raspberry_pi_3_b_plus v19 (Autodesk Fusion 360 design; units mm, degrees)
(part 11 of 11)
sketch "Sketch3" plane through (0, 0, -5) normal (0, 0, -1) x axis (1, 0, 0)
  line L1 (-45.553, 29.75) -> (-52.5, 29.75)
  line L2 (-45.553, -29.75) -> (-45.553, 29.75)
  line L3 (-52.5, -29.75) -> (-45.553, -29.75)
  line L4 (-52.5, 29.75) -> (-52.5, -29.75)
  line L5 (44.5, 29.75) -> (-52.5, 29.75)
  line L6 (-52.5, 29.75) -> (-52.5, 24)
  line L7 (-42.0889, 24) -> (-43.8209, 21)
  line L8 (-43.8209, 27) -> (-42.0889, 24)
  line L9 (-47.2851, 27) -> (-43.8209, 27)
  line L10 (-49.0171, 24) -> (-47.2851, 27)
  line L11 (-47.2851, 21) -> (-49.0171, 24)
  line L12 (-43.8209, 21) -> (-47.2851, 21)
  line L13 (-43.8209, 19) -> (-42.0889, 16)
  line L14 (-49.0171, 16) -> (-47.2851, 19)
  line L15 (-47.2851, 19) -> (-43.8209, 19)
  line L16 (-47.2851, 13) -> (-49.0171, 16)
  line L17 (-43.8209, 13) -> (-47.2851, 13)
  line L18 (-42.0889, 16) -> (-43.8209, 13)
  line L19 (-43.8209, 11) -> (-42.0889, 8)
  line L20 (-49.0171, 8) -> (-47.2851, 11)
  line L21 (-47.2851, 11) -> (-43.8209, 11)
  line L22 (-47.2851, 5) -> (-49.0171, 8)
  line L23 (-43.8209, 5) -> (-47.2851, 5)
  line L24 (-42.0889, 8) -> (-43.8209, 5)
  line L25 (-43.8209, 3) -> (-42.0889, 0)
  line L26 (-49.0171, 0) -> (-47.2851, 3)
  line L27 (-47.2851, 3) -> (-43.8209, 3)
  line L28 (-47.2851, -3) -> (-49.0171, 0)
  line L29 (-43.8209, -3) -> (-47.2851, -3)
  line L30 (-42.0889, 0) -> (-43.8209, -3)
  line L31 (-43.8209, -5) -> (-42.0889, -8)
  line L32 (-49.0171, -8) -> (-47.2851, -5)
  line L33 (-47.2851, -5) -> (-43.8209, -5)
  line L34 (-47.2851, -11) -> (-49.0171, -8)
  line L35 (-43.8209, -11) -> (-47.2851, -11)
  line L36 (-42.0889, -8) -> (-43.8209, -11)
  line L37 (-43.8209, -13) -> (-42.0889, -16)
  line L38 (-49.0171, -16) -> (-47.2851, -13)
  line L39 (-47.2851, -13) -> (-43.8209, -13)
  line L40 (-47.2851, -19) -> (-49.0171, -16)
  line L41 (-43.8209, -19) -> (-47.2851, -19)
  line L42 (-42.0889, -16) -> (-43.8209, -19)
  line L43 (-43.8209, -21) -> (-42.0889, -24)
  line L44 (-49.0171, -24) -> (-47.2851, -21)
  line L45 (-47.2851, -21) -> (-43.8209, -21)
  line L46 (-47.2851, -27) -> (-49.0171, -24)
  line L47 (-43.8209, -27) -> (-47.2851, -27)
  line L48 (-42.0889, -24) -> (-43.8209, -27)
  line L49 (-41.2229, 21.5) -> (-42.9549, 22.5)
  line L50 (-41.2229, 18.5) -> (-42.9549, 17.5)
  line L51 (-38.6248, 20) -> (-41.2229, 18.5)
  line L52 (-38.6248, 20) -> (-41.2229, 21.5)
  line L53 (-40.3568, 17) -> (-42.0889, 20)
  line L54 (-36.8927, 17) -> (-40.3568, 17)
  line L55 (-35.1607, 20) -> (-36.8927, 17)
  line L56 (-36.8927, 23) -> (-35.1607, 20)
  line L57 (-40.3568, 23) -> (-36.8927, 23)
  line L58 (-42.0889, 20) -> (-40.3568, 23)
  line L59 (-40.3568, 15) -> (-36.8927, 15)
  line L60 (-36.8927, 15) -> (-35.1607, 12)
  line L61 (-35.1607, 12) -> (-36.8927, 9)
  line L62 (-36.8927, 9) -> (-40.3568, 9)
  line L63 (-40.3568, 9) -> (-42.0889, 12)
  line L64 (-42.0889, 12) -> (-40.3568, 15)
  line L65 (-40.3568, 7) -> (-36.8927, 7)
  line L66 (-36.8927, 7) -> (-35.1607, 4)
  line L67 (-35.1607, 4) -> (-36.8927, 1)
  line L68 (-36.8927, 1) -> (-40.3568, 1)
  line L69 (-40.3568, 1) -> (-42.0889, 4)
  line L70 (-42.0889, 4) -> (-40.3568, 7)
  line L71 (-40.3568, -1) -> (-36.8927, -1)
  line L72 (-36.8927, -1) -> (-35.1607, -4)
  line L73 (-35.1607, -4) -> (-36.8927, -7)
  line L74 (-36.8927, -7) -> (-40.3568, -7)
  line L75 (-40.3568, -7) -> (-42.0889, -4)
  line L76 (-42.0889, -4) -> (-40.3568, -1)
  line L77 (-40.3568, -9) -> (-36.8927, -9)
  line L78 (-36.8927, -9) -> (-35.1607, -12)
  line L79 (-35.1607, -12) -> (-36.8927, -15)
  line L80 (-36.8927, -15) -> (-40.3568, -15)
  line L81 (-40.3568, -15) -> (-42.0889, -12)
  line L82 (-42.0889, -12) -> (-40.3568, -9)
  line L83 (-40.3568, -17) -> (-36.8927, -17)
  line L84 (-36.8927, -17) -> (-35.1607, -20)
  line L85 (-35.1607, -20) -> (-36.8927, -23)
  line L86 (-36.8927, -23) -> (-40.3568, -23)
  line L87 (-40.3568, -23) -> (-42.0889, -20)
  line L88 (-42.0889, -20) -> (-40.3568, -17)
  line L89 (-23.0367, 9) -> (-26.5008, 9)
  line L90 (-29.9649, 11) -> (-28.2329, 8)
  line L91 (-28.2329, -16) -> (-29.9649, -19)
  line L92 (-35.1611, 8) -> (-33.4291, 11)
  line L93 (-29.9649, 13) -> (-33.4291, 13)
  line L94 (-35.1611, -16) -> (-33.4291, -13)
  line L95 (-29.9649, 21) -> (-33.4291, 21)
  line L96 (-26.5008, 23) -> (-23.0367, 23)
  line L97 (-23.0367, 17) -> (-26.5008, 17)
  line L98 (-26.5008, 17) -> (-28.2329, 20)
  line L99 (-29.9649, 19) -> (-28.2329, 16)
  line L100 (-26.5008, 15) -> (-23.0367, 15)
  line L101 (-26.5008, 7) -> (-23.0367, 7)
  line L102 (-23.0367, -7) -> (-26.5008, -7)
  line L103 (-28.2329, -12) -> (-26.5008, -9)
  line L104 (-33.4291, 21) -> (-35.1611, 24)
  line L105 (-21.3047, -20) -> (-23.0367, -23)
  line L106 (-21.3047, 4) -> (-23.0367, 1)
  line L107 (-21.3047, 12) -> (-23.0367, 9)
  line L108 (-33.4291, -5) -> (-29.9649, -5)
  line L109 (-33.4291, -3) -> (-35.1611, 0)
  line L110 (-29.9649, -11) -> (-33.4291, -11)
  line L111 (-21.3047, -12) -> (-23.0367, -15)
  line L112 (-26.5008, -7) -> (-28.2329, -4)
  line L113 (-28.2329, -20) -> (-26.5008, -17)
  line L114 (-33.4291, 19) -> (-29.9649, 19)
  line L115 (-23.0367, -17) -> (-21.3047, -20)
  line L116 (-29.9649, -13) -> (-28.2329, -16)
  line L117 (-33.4291, 27) -> (-29.9649, 27)
  line L118 (-21.3047, -4) -> (-23.0367, -7)
  line L119 (-26.5008, 1) -> (-28.2329, 4)
  line L120 (-28.2329, -8) -> (-29.9649, -11)
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  point P14 (-45.553, 24)
  point P63 (-42.9549, 22.5)
  point P65 (-42.9549, 17.5)
  point P67 (-38.6248, 20)
  point P74 (-38.6248, 20)
  point P395 (-34.5, -1.25)
  point P642 (-34.5, -1.25)
  point P64 (-41.2229, 21.5)
  point P66 (-41.2229, 18.5)
  point P643 (-34.5, 4.75)
  point P644 (-59.5, 4.75)
  point P645 (50.5, 4.75)
  point P647 (-59.5, -7.25)
  horizontal L1
  vertical L2
  horizontal L3
  vertical L4
  horizontal L5
  vertical L6
  coincident L2 P14
  midpoint L7 P63
  perpendicular L7 L49
  midpoint L13 P65
  perpendicular L13 L50
  parallel L50 L51
  perpendicular L7 L52
  coincident P67 P74
  coincident P395 P642
  dimension "d18" = 14.25
  dimension "d18" = 14.25
  dimension "d720" distance P14 L12 = 3
  dimension "d725" distance P63 P64 = 2
  dimension "d726" distance P65 P66 = 2
  dimension "d727" distance P74 L58 = 3
  dimension "d756" distance P642 P643 = 6
  dimension "d757" distance P643 P644 = 25
  dimension "d758" distance P644 P645 = 110
  dimension "d759" distance P644 P647 = 12
  dimension "d718" distance = 6.947
  dimension "d719" distance = 5.75
  dimension "d723" R-Pattern1-uDistance = 0
  dimension "d724" R-Pattern1-vDistance = -8
  dimension "d730" R-Pattern2-uDistance = 0
  dimension "d731" R-Pattern2-vDistance = -8
sketch "Sketch4" plane through (0, 0, 20) normal (0, 0, 1) x axis (-1, 0, 0)
  line L1 (-14.5, 1.25) -> (-30.5, 1.25)
  line L2 (-14.5, -3.75) -> (-14.5, 1.25)
  line L3 (-30.5, -3.75) -> (-14.5, -3.75)
  line L4 (-30.5, 1.25) -> (-30.5, -3.75)
  line L5 (-44.5, -26.75) -> (-44.5, 26.75)
  line L6 (42.5, 1.25) -> (26.5, 1.25)
  line L7 (42.5, -3.75) -> (42.5, 1.25)
  line L8 (26.5, -3.75) -> (42.5, -3.75)
  line L9 (26.5, 1.25) -> (26.5, -3.75)
  line L10 (-0.7829, 5.1511) -> (-0.7829, 28.1511)
  line L11 (-4.7829, 5.1511) -> (-0.7829, 5.1511)
  line L12 (-4.7829, 28.1511) -> (-4.7829, 5.1511)
  line L13 (-0.7829, 28.1511) -> (-4.7829, 28.1511)
  line L14 (2.3829, -5) -> (5.8471, -5)
  line L15 (-32.2568, -17) -> (-28.7927, -17)
  line L16 (-20.1329, 8) -> (-21.8649, 5)
  line L17 (-32.2568, -15) -> (-33.9889, -12)
  line L18 (28.3629, 0) -> (30.0949, 3)
  line L19 (-14.9367, 7) -> (-13.2047, 4)
  line L20 (-21.8649, -19) -> (-25.3291, -19)
  line L21 (-25.3291, -13) -> (-21.8649, -13)
  line L22 (-33.9889, -20) -> (-32.2568, -17)
  line L23 (-6.2769, 4) -> (-4.5448, 7)
  line L24 (-33.9889, 8) -> (-35.7209, 5)
  line L25 (2.3829, -13) -> (5.8471, -13)
  line L26 (33.5591, 3) -> (35.2911, 0)
  line L27 (19.7031, 3) -> (21.4351, 0)
  line L28 (2.3829, 5) -> (0.6509, 8)
  line L29 (-11.4731, 5) -> (-13.2051, 8)
  line L30 (-1.0807, 7) -> (0.6513, 4)
  line L31 (-40.9171, -16) -> (-39.1851, -13)
  line L32 (-28.7927, -15) -> (-32.2568, -15)
  line L33 (-27.0611, -24) -> (-25.3291, -21)
  line L34 (-28.7927, 7) -> (-27.0607, 4)
  line L35 (47.4151, 3) -> (49.1471, 0)
  line L36 (37.0232, 1) -> (35.2911, 4)
  line L37 (-27.0607, -20) -> (-28.7927, -23)
  line L38 (-25.3291, 5) -> (-27.0611, 8)
  line L39 (-33.9889, 4) -> (-32.2568, 7)
  line L40 (-28.7927, -17) -> (-27.0607, -20)
  line L41 (-1.0807, -9) -> (0.6513, -12)
  line L42 (14.5073, 4) -> (12.7753, 1)
  line L43 (-40.9171, -24) -> (-39.1851, -21)
  line L44 (-20.1329, 4) -> (-18.4008, 7)
  line L45 (-21.8649, 21) -> (-25.3291, 21)
  line L46 (-33.9889, -12) -> (-32.2568, -9)
  line L47 (-20.1329, -12) -> (-18.4008, -9)
  line L48 (14.5069, -16) -> (16.2389, -13)
  line L49 (16.2389, -21) -> (19.7031, -21)
  line L50 (9.3112, 1) -> (7.5791, 4)
  line L51 (-39.1851, -19) -> (-40.9171, -16)
  line L52 (14.5069, 0) -> (16.2389, 3)
  line L53 (-21.8649, 13) -> (-25.3291, 13)
  line L54 (-18.4008, -7) -> (-20.1329, -4)
  line L55 (-14.9367, -9) -> (-13.2047, -12)
  line L56 (-39.1851, 5) -> (-40.9171, 8)
  line L57 (28.3633, 4) -> (26.6313, 1)
  line L58 (-18.4008, -23) -> (-20.1329, -20)
  line L59 (43.9509, -13) -> (47.4151, -13)
  line L60 (-6.2769, -12) -> (-4.5448, -9)
  line L61 (-25.3291, 11) -> (-21.8649, 11)
  line L62 (42.2189, 0) -> (43.9509, 3)
  line L63 (-28.7927, -23) -> (-32.2568, -23)
  line L64 (-25.3291, 19) -> (-21.8649, 19)
  line L65 (-25.3291, 27) -> (-21.8649, 27)
  line L66 (5.8471, -13) -> (7.5791, -16)
  line L67 (42.2193, 4) -> (40.4873, 1)
  line L68 (-6.2769, 8) -> (-8.0089, 5)
  line L69 (-28.7927, -9) -> (-27.0607, -12)
  line L70 (23.1672, 1) -> (21.4351, 4)
  line L71 (-18.4008, 1) -> (-20.1329, 4)
  line L72 (5.8471, 3) -> (7.5791, 0)
  line L73 (-25.3291, -21) -> (-21.8649, -21)
  line L74 (-35.7209, -21) -> (-33.9889, -24)
  line L75 (28.3629, 16) -> (30.0949, 19)
  line L76 (-21.8649, -13) -> (-20.1329, -16)
  line L77 (28.3629, 8) -> (30.0949, 11)
  line L78 (16.2389, 27) -> (19.7031, 27)
  line L79 (47.4151, -19) -> (43.9509, -19)
  line L80 (-4.5448, 23) -> (-1.0807, 23)
  line L81 (-20.1329, -4) -> (-18.4008, -1)
  line L82 (-39.1851, -21) -> (-35.7209, -21)
  line L83 (47.4151, -3) -> (43.9509, -3)
  line L84 (9.3112, -17) -> (12.7753, -17)
  line L85 (30.0949, 5) -> (28.3629, 8)
  line L86 (-1.0807, 17) -> (-4.5448, 17)
  line L87 (-33.9889, 16) -> (-35.7209, 13)
  line L88 (-21.8649, -27) -> (-25.3291, -27)
  line L89 (-14.9367, -7) -> (-18.4008, -7)
  line L90 (43.9509, -5) -> (47.4151, -5)
  line L91 (30.0949, 21) -> (28.3629, 24)
  line L92 (-18.4008, -15) -> (-20.1329, -12)
  line L93 (-18.4008, -1) -> (-14.9367, -1)
  line L94 (14.5073, -12) -> (12.7753, -15)
  line L95 (-11.4731, 19) -> (-8.0089, 19)
  line L96 (-25.3291, -19) -> (-27.0611, -16)
  line L97 (9.3112, -23) -> (7.5791, -20)
  line L98 (-39.1851, 13) -> (-40.9171, 16)
  line L99 (-8.0089, 27) -> (-6.2769, 24)
  line L100 (-39.1851, -27) -> (-40.9171, -24)
  line L101 (30.0949, 13) -> (28.3629, 16)
  line L102 (-35.7209, 11) -> (-33.9889, 8)
  line L103 (-6.2769, 0) -> (-8.0089, -3)
  line L104 (19.7031, 5) -> (16.2389, 5)
  line L105 (-35.7209, 19) -> (-33.9889, 16)
  line L106 (-32.2568, 15) -> (-28.7927, 15)
  line L107 (28.3629, 24) -> (30.0949, 27)
  line L108 (21.4351, -16) -> (19.7031, -19)
  line L109 (-35.7209, -19) -> (-39.1851, -19)
  line L110 (35.2911, 16) -> (33.5591, 13)
  line L111 (-20.1329, -16) -> (-21.8649, -19)
  line L112 (12.7753, -23) -> (9.3112, -23)
  line L113 (-8.0089, 11) -> (-6.2769, 8)
  line L114 (0.6513, 4) -> (-1.0807, 1)
  line L115 (-25.3291, 13) -> (-27.0611, 16)
  line L116 (-20.1329, -20) -> (-18.4008, -17)
  line L117 (19.7031, -19) -> (16.2389, -19)
  line L118 (-32.2568, -23) -> (-33.9889, -20)
  line L119 (-11.4731, 27) -> (-8.0089, 27)
  line L120 (-33.9889, -24) -> (-35.7209, -27)
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  point P147 (-34.8549, 17.5)
  point P23 (-30.5248, 20)
  point P24 (-30.5248, 20)
  point P10 (42.5, -3.75)
  point P633 (42.5, -3.75)
  point P8 (26.5, 1.25)
  point P634 (26.5, 1.25)
  point P136 (-34.8549, 22.5)
  point P137 (-33.1229, 21.5)
  point P149 (-33.1229, 18.5)
  point P635 (34.5, -1.25)
  point P636 (34.5, -7.25)
  point P637 (59, -7.25)
  point P638 (-51, -7.25)
  point P640 (59, 4.75)
  midpoint P147 L105
  coincident P23 P24
  coincident P10 P633
  coincident P8 P634
  dimension "d748" distance = 3
  dimension "d749" distance P136 P137 = 2
  dimension "d750" distance P147 P149 = 2
  dimension "d751" distance = 3
  dimension "d762" distance P635 P636 = 6
  dimension "d763" distance P637 P638 = 110
  dimension "d764" distance P637 P640 = 12
  dimension "d742" R-Pattern1-uDistance = 0
  dimension "d743" R-Pattern1-vDistance = -8
extrude "Extrude31" cut sketch "Sketch3" against normal blind 3
extrude "Extrude32" cut sketch "Sketch4" against normal blind 3
split "Split1" bodies "Top (1)", "Top (2)"
sketch "Sketch22" plane through (0, 0, 20) normal (0, 0, -1) x axis (1, 0, 0)
  line L1 (-26.5, 1.25) -> (-26.5, -3.75)
  line L2 (-42.5, 1.25) -> (-26.5, 1.25)
  line L3 (-42.5, -3.75) -> (-42.5, 1.25)
  line L4 (-26.5, -3.75) -> (-42.5, -3.75)
  line L5 (-26.5, -3.75) -> (-42.5, 1.25)
  line L6 (-40.5, 0.25) -> (-28.5, 0.25)
  line L7 (-40.5, -2.75) -> (-40.5, 0.25)
  line L8 (-28.5, -2.75) -> (-40.5, -2.75)
  line L9 (-28.5, 0.25) -> (-28.5, -2.75)
  line L10 (-40.5, -2.75) -> (-28.5, 0.25)
  line L11 (-28.5, -2.75) -> (-40.5, 0.25)
  line L12 (30.5, -3.75) -> (14.5, 1.25)
  line L13 (28.5, -2.75) -> (16.5, -2.75)
  line L14 (28.5, 0.25) -> (28.5, -2.75)
  line L15 (16.5, 0.25) -> (28.5, 0.25)
  line L16 (16.5, -2.75) -> (16.5, 0.25)
  line L17 (28.5, 0.25) -> (16.5, -2.75)
  line L18 (16.5, 0.25) -> (28.5, -2.75)
  point P4 (-42.5, 1.25)
  point P6 (-42.5, 1.25)
  point P2 (-26.5, -3.75)
  point P7 (-26.5, -3.75)
  point P12 (-34.5, -1.25)
  point P13 (14.5, 1.25)
  point P15 (14.5, 1.25)
  point P14 (30.5, -3.75)
  point P16 (30.5, -3.75)
  point P21 (22.5, -1.25)
  point P10 (-40.5, -2.75)
  point P11 (-28.5, -2.75)
  point P9 (-40.5, 0.25)
  point P19 (28.5, 0.25)
  point P20 (16.5, 0.25)
  point P18 (28.5, -2.75)
  coincident P4 P6
  coincident P2 P7
  horizontal L6
  perpendicular L6 L7
  parallel L6 L8
  parallel L7 L9
  coincident L10 P12
  coincident L11 P12
  midpoint L5 P12
  coincident P13 P15
  coincident P14 P16
  horizontal L13
  perpendicular L13 L14
  parallel L13 L15
  parallel L14 L16
  coincident L17 P21
  coincident L18 P21
  midpoint L12 P21
  dimension "d767" distance P10 P11 = 12
  dimension "d768" distance P9 P10 = 3
  dimension "d769" distance P19 P20 = 12
  dimension "d770" distance P18 P19 = 3
extrude "Extrude33" add sketch "Sketch22" profile of L6 L7 L8 L9 L13 L14 L15 L16 along normal blind 1.5
extrude "Extrude34" cut sketch "Sketch22" profile of L6 L7 L8 L9 L13 L14 L15 L16 along normal blind 1.5
split "Split2" bodies "Bottom (1)", "Bottom (2)"
sketch "Sketch23" plane through (0, 0, -5) normal (0, 0, -1) x axis (1, 0, 0)
  line L1 (14.5, 1.25) -> (30.5, -3.75)
  line L2 (-42.5, 1.25) -> (-26.5, -3.75)
  line L3 (-40.5, -2.75) -> (-28.5, -2.75)
  line L4 (-40.5, 0.25) -> (-40.5, -2.75)
  line L5 (-28.5, 0.25) -> (-40.5, 0.25)
  line L6 (-28.5, -2.75) -> (-28.5, 0.25)
  line L7 (-40.5, 0.25) -> (-28.5, -2.75)
  line L8 (-28.5, 0.25) -> (-40.5, -2.75)
  line L9 (16.5, -2.75) -> (28.5, -2.75)
  line L10 (16.5, 0.25) -> (16.5, -2.75)
  line L11 (28.5, 0.25) -> (16.5, 0.25)
  line L12 (28.5, -2.75) -> (28.5, 0.25)
  line L13 (16.5, 0.25) -> (28.5, -2.75)
  line L14 (28.5, 0.25) -> (16.5, -2.75)
  line L15 (-52.5, -26.75) -> (-52.5, 26.75)
  line L16 (40.5, -30.75) -> (-48.5, -30.75)
  line L17 (44.5, 26.75) -> (44.5, -26.75)
  line L18 (-48.5, 30.75) -> (40.5, 30.75)
  line L19 (8.1389, -21) -> (6.4069, -24)
  line L20 (11.6031, -21) -> (8.1389, -21)
  line L21 (13.3351, -24) -> (11.6031, -21)
  line L22 (11.6031, -27) -> (13.3351, -24)
  line L23 (8.1389, -27) -> (11.6031, -27)
  line L24 (6.4069, -24) -> (8.1389, -27)
  line L25 (-2.2529, -19) -> (-0.5209, -16)
  line L26 (-5.7171, -19) -> (-2.2529, -19)
  line L27 (-7.4491, -16) -> (-5.7171, -19)
  line L28 (-5.7171, -13) -> (-7.4491, -16)
  line L29 (-2.2529, -13) -> (-5.7171, -13)
  line L30 (-0.5209, -16) -> (-2.2529, -13)
  line L31 (-23.0367, -23) -> (-21.3047, -20)
  line L32 (-26.5008, -23) -> (-23.0367, -23)
  line L33 (-28.2329, -20) -> (-26.5008, -23)
  line L34 (-26.5008, -17) -> (-28.2329, -20)
  line L35 (-23.0367, -17) -> (-26.5008, -17)
  line L36 (-21.3047, -20) -> (-23.0367, -17)
  line L37 (-23.0367, -15) -> (-21.3047, -12)
  line L38 (-26.5008, -15) -> (-23.0367, -15)
  line L39 (-28.2329, -12) -> (-26.5008, -15)
  line L40 (-26.5008, -9) -> (-28.2329, -12)
  line L41 (-23.0367, -9) -> (-26.5008, -9)
  line L42 (-21.3047, -12) -> (-23.0367, -9)
  line L43 (32.3873, -15) -> (34.1193, -12)
  line L44 (28.9232, -15) -> (32.3873, -15)
  line L45 (27.1911, -12) -> (28.9232, -15)
  line L46 (28.9232, -9) -> (27.1911, -12)
  line L47 (32.3873, -9) -> (28.9232, -9)
  line L48 (34.1193, -12) -> (32.3873, -9)
  line L49 (-0.9539, -7.25) -> (-7.0161, -7.25)
  line L50 (-0.5209, -8) -> (-0.9539, -7.25)
  line L51 (-2.2529, -11) -> (-0.5209, -8)
  line L52 (-5.7171, -11) -> (-2.2529, -11)
  line L53 (-7.4491, -8) -> (-5.7171, -11)
  line L54 (-7.0161, -7.25) -> (-7.4491, -8)
  line L55 (13.7681, 4.75) -> (19.8303, 4.75)
  line L56 (15.0672, 7) -> (13.7681, 4.75)
  line L57 (18.5313, 7) -> (15.0672, 7)
  line L58 (19.8303, 4.75) -> (18.5313, 7)
  line L59 (-13.9439, 4.75) -> (-7.8817, 4.75)
  line L60 (-12.6448, 7) -> (-13.9439, 4.75)
  line L61 (-9.1807, 7) -> (-12.6448, 7)
  line L62 (-7.8817, 4.75) -> (-9.1807, 7)
  line L63 (8.1389, 11) -> (6.4069, 8)
  line L64 (11.6031, 11) -> (8.1389, 11)
  line L65 (13.3351, 8) -> (11.6031, 11)
  line L66 (11.6031, 5) -> (13.3351, 8)
  line L67 (8.1389, 5) -> (11.6031, 5)
  line L68 (6.4069, 8) -> (8.1389, 5)
  line L69 (-26.5008, 9) -> (-23.0367, 9)
  line L70 (-28.2329, 12) -> (-26.5008, 9)
  line L71 (-26.5008, 15) -> (-28.2329, 12)
  line L72 (-23.0367, 15) -> (-26.5008, 15)
  line L73 (-21.3047, 12) -> (-23.0367, 15)
  line L74 (-23.0367, 9) -> (-21.3047, 12)
  line L75 (1.2112, 9) -> (4.6753, 9)
  line L76 (-0.5209, 12) -> (1.2112, 9)
  line L77 (1.2112, 15) -> (-0.5209, 12)
  line L78 (4.6753, 15) -> (1.2112, 15)
  line L79 (6.4073, 12) -> (4.6753, 15)
  line L80 (4.6753, 9) -> (6.4073, 12)
  line L81 (41.0471, 16) -> (39.3151, 19)
  line L82 (39.3151, 13) -> (41.0471, 16)
  line L83 (35.8509, 13) -> (39.3151, 13)
  line L84 (34.1189, 16) -> (35.8509, 13)
  line L85 (35.8509, 19) -> (34.1189, 16)
  line L86 (39.3151, 19) -> (35.8509, 19)
  line L87 (6.4073, 20) -> (4.6753, 23)
  line L88 (4.6753, 17) -> (6.4073, 20)
  line L89 (1.2112, 17) -> (4.6753, 17)
  line L90 (-0.5209, 20) -> (1.2112, 17)
  line L91 (1.2112, 23) -> (-0.5209, 20)
  line L92 (4.6753, 23) -> (1.2112, 23)
  line L93 (-16.1089, 27) -> (-19.5731, 27)
  line L94 (-14.3769, 24) -> (-16.1089, 27)
  line L95 (-16.1089, 21) -> (-14.3769, 24)
  line L96 (-19.5731, 21) -> (-16.1089, 21)
  line L97 (-21.3051, 24) -> (-19.5731, 21)
  line L98 (-19.5731, 27) -> (-21.3051, 24)
  line L99 (-2.2529, 27) -> (-5.7171, 27)
  line L100 (-0.5209, 24) -> (-2.2529, 27)
  line L101 (-2.2529, 21) -> (-0.5209, 24)
  line L102 (-5.7171, 21) -> (-2.2529, 21)
  line L103 (-7.4491, 24) -> (-5.7171, 21)
  line L104 (-5.7171, 27) -> (-7.4491, 24)
  line L105 (11.6031, 27) -> (8.1389, 27)
  line L106 (13.3351, 24) -> (11.6031, 27)
  line L107 (11.6031, 21) -> (13.3351, 24)
  line L108 (8.1389, 21) -> (11.6031, 21)
  line L109 (6.4069, 24) -> (8.1389, 21)
  line L110 (8.1389, 27) -> (6.4069, 24)
  line L111 (28.9232, 9) -> (32.3873, 9)
  line L112 (27.1911, 12) -> (28.9232, 9)
  line L113 (28.9232, 15) -> (27.1911, 12)
  line L114 (32.3873, 15) -> (28.9232, 15)
  line L115 (34.1193, 12) -> (32.3873, 15)
  line L116 (32.3873, 9) -> (34.1193, 12)
  line L117 (-0.5209, 16) -> (-2.2529, 19)
  line L118 (-2.2529, 13) -> (-0.5209, 16)
  line L119 (-5.7171, 13) -> (-2.2529, 13)
  line L120 (-7.4491, 16) -> (-5.7171, 13)
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  point P10 (-34.5, -1.25)
  point P15 (22.5, -1.25)
  point P8 (-40.5, 0.25)
  point P9 (-28.5, 0.25)
  point P7 (-40.5, -2.75)
  point P13 (16.5, 0.25)
  point P14 (28.5, 0.25)
  point P12 (16.5, -2.75)
  horizontal L3
  perpendicular L3 L4
  parallel L3 L5
  parallel L4 L6
  coincident L7 P10
  coincident L8 P10
  midpoint L2 P10
  horizontal L9
  perpendicular L9 L10
  parallel L9 L11
  parallel L10 L12
  coincident L13 P15
  coincident L14 P15
  midpoint L1 P15
  dimension "d775" distance P8 P9 = 12
  dimension "d776" distance P7 P8 = 3
  dimension "d777" distance P13 P14 = 12
  dimension "d778" distance P12 P13 = 3
extrude "Extrude35" add sketch "Sketch23" profile of L3 L4 L5 L6 L9 L10 L11 L12 against normal blind 1.5
extrude "Extrude36" cut sketch "Sketch23" profile of L3 L4 L5 L6 L9 L10 L11 L12 against normal blind 1.5
extrude "Extrude37" cut sketch "Sketch4" profile of L1 L3 L4 against normal blind 1.5
extrude "Extrude9" cut sketch "Sketch3" profile of L1 L2 L3 L4 against normal blind 1.5
extrude "Extrude39" add sketch "Sketch2" profile of C1 C2 C3 C4 C5 C6 C7 C8 against normal blind 5
extrude "Extrude40" add sketch "Sketch2" profile of C5 C6 C7 C8 against normal blind 6.68
extrude "Extrude41" add sketch "Sketch8" no distance stored
fillet "Fillet1" radius 0.4
work_plane "WorkPlane16" AlongDistance 0
sketch "Sketch24" plane through (-4.0084, 0, 9) normal (0, 0, 1) x axis (1, 0, 0)
  line L1 (-43.9916, -16.75) -> (-43.9916, -26.75)
  line L2 (-46.9916, -16.75) -> (-43.9916, -16.75)
  line L3 (-46.9916, -26.75) -> (-46.9916, -16.75)
  line L4 (-44.4916, -29.25) -> (-32.8938, -29.25)
  line L5 (-43.9916, -29.25) -> (-43.9916, -26.75)
  line L6 (-43.9916, 16.75) -> (-43.9916, 26.75)
  line L7 (-46.9916, 16.75) -> (-43.9916, 16.75)
  line L8 (-46.9916, 26.75) -> (-46.9916, 16.75)
  line L9 (44.5084, 29.25) -> (-44.4916, 29.25)
  line L10 (-43.9916, 29.25) -> (-43.9916, 26.75)
  line L11 (-44.4916, 29.25) -> (-43.9916, 29.25)
  line L12 (34.5084, 29.25) -> (44.5084, 29.25)
  line L13 (34.5084, 26.25) -> (34.5084, 29.25)
  line L14 (44.5084, 26.25) -> (34.5084, 26.25)
  line L15 (44.5084, 26.25) -> (47.0084, 27.1157)
  line L16 (34.5084, -29.25) -> (44.5084, -29.25)
  line L17 (34.5084, -26.25) -> (34.5084, -29.25)
  line L18 (44.5084, -26.25) -> (34.5084, -26.25)
  line L19 (47.0084, -26.8856) -> (44.5084, -26.25)
  arc A1 centre (-44.4916, -26.75) radius 2.5 clockwise from (-44.4916, -29.25) to (-46.9916, -26.75)
  arc A2 centre (-44.4916, 26.75) radius 2.5 clockwise from (-46.9916, 26.75) to (-44.4916, 29.25)
  arc A3 centre (44.5084, 26.75) radius 2.5 clockwise from (44.5084, 29.25) to (46.9828, 27.1068)
  arc A4 centre (44.5084, -26.75) radius 2.5 clockwise from (47.0047, -26.8847) to (44.5084, -29.25)
  point P4 (-44.4916, -26.75)
  point P5 (-44.4916, -26.75)
  point P2 (-46.9916, -26.75)
  point P6 (-46.9916, -26.75)
  point P12 (-43.9916, -29.25)
  point P13 (-44.4916, 26.75)
  point P14 (-44.4916, 26.75)
  point P15 (-46.9916, 26.75)
  point P19 (-46.9916, 26.75)
  point P22 (-43.9916, 29.25)
  point P20 (-44.4916, 29.25)
  point P23 (-44.4916, 29.25)
  point P24 (44.5084, 26.75)
  point P25 (44.5084, 26.75)
  point P21 (44.5084, 29.25)
  point P26 (44.5084, 29.25)
  point P30 (47.0084, 27.1157)
  point P31 (47.0084, 27.1157)
  point P32 (46.9828, 27.1068)
  point P33 (44.5084, -26.75)
  point P34 (44.5084, -26.75)
  point P35 (44.5084, -29.25)
  point P39 (44.5084, -29.25)
  point P40 (47.0084, -26.8856)
  point P41 (47.0084, -26.8856)
  point P42 (47.0047, -26.8847)
  point P7 (-43.9916, -26.75)
  point P9 (-46.9916, -16.75)
  point P16 (-43.9916, 26.75)
  point P18 (-46.9916, 16.75)
  point P27 (34.5084, 29.25)
  point P29 (44.5084, 26.25)
  point P36 (34.5084, -29.25)
  point P38 (44.5084, -26.25)
  coincident P4 P5
  vertical L1
  horizontal L2
  vertical L3
  coincident P2 P6
  coincident L4 P12
  coincident P13 P14
  vertical L6
  horizontal L7
  vertical L8
  coincident P15 P19
  coincident L9 P22
  coincident P20 P23
  tangent L11 A2
  coincident P24 P25
  horizontal L12
  vertical L13
  horizontal L14
  coincident P21 P26
  coincident P30 P31
  coincident L15 P32
  coincident P33 P34
  horizontal L16
  vertical L17
  horizontal L18
  coincident P35 P39
  coincident P40 P41
  coincident L19 P42
  dimension "d813" distance P6 P7 = 3
  dimension "d814" distance P6 P9 = 10
  dimension "d815" distance P15 P16 = 3
  dimension "d816" distance P15 P18 = 10
  dimension "d817" distance P26 P27 = 10
  dimension "d818" distance P26 P29 = 3
  dimension "d819" distance P35 P36 = 10
  dimension "d820" distance P35 P38 = 3
extrude "Extrude42" add sketch "Sketch24" distance 4
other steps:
extrude "Extrude38" cut sketch "Sketch3" profile of L1 L2 L3 L4 against normal blind 1.5
create_component "CreateComponent1"
create_component "CreateComponent1"
create_component "CreateComponent2"
create_component "CreateComponent4"
create_component "CreateComponent5"
create_component "CreateComponent2"
create_component "CreateComponent1"
create_component "CreateComponent1"
create_component "CreateComponent2"
create_component "CreateComponent3"
create_component "CreateComponent1"
create_component "CreateComponent2"
create_component "CreateComponent3"
create_component "CreateComponent4"
create_component "CreateComponent5"
create_component "CreateComponent3"
create_component "CreateComponent2"
create_component "CreateComponent4"
create_component "CreateComponent1"
create_component "CreateComponent7"
create_component "CreateComponent8"
create_component "CreateComponent11"
create_component "CreateComponent12"
create_component "CreateComponent1"
create_component "CreateComponent16"
create_component "CreateComponent1"
create_component "CreateComponent1"
create_component "CreateComponent2"
create_component "CreateComponent2"
create_component "CreateComponent1"
create_component "CreateComponent3"
create_component "CreateComponent3"
create_component "CreateComponent2"
create_component "CreateComponent3"
create_component "CreateComponent17"
create_component "CreateComponent1"
create_component "CreateComponent1"
create_component "CreateComponent2"
create_component "CreateComponent2"
create_component "CreateComponent1"
create_component "CreateComponent3"
create_component "CreateComponent3"
create_component "CreateComponent2"
create_component "CreateComponent3"
create_component "CreateComponent18"
create_component "CreateComponent2"
create_component "CreateComponent4"
create_component "CreateComponent1"
create_component "CreateComponent19"
create_component "CreateComponent6"
create_component "CreateComponent7"
create_component "CreateComponent1"
create_component "CreateComponent8"
create_component "CreateComponent9"
create_component "CreateComponent1"
create_component "CreateComponent2"
create_component "CreateComponent3"
create_component "CreateComponent20"
create_component "CreateComponent1"
create_component "CreateComponent2"
create_component "CreateComponent3"
create_component "CreateComponent4"
create_component "CreateComponent21"
create_component "CreateComponent1"
create_component "CreateComponent22"
create_component "CreateComponent24"
named bodies: "lead2", "lead1", "lead3", "Top", "Top (1)", "Top (2)", "Bottom (1)", "Bottom (2)"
